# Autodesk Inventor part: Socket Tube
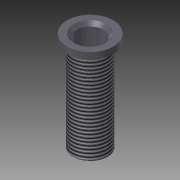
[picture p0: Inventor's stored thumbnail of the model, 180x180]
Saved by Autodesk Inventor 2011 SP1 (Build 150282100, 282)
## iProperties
Created: 2011-10
Part Number: Socket Tube
Document SubType Name: Modeling
Designer: sdarley
Density: 1 g/cm^3
Author: sdarley
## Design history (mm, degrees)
sketch "Sketch1"
  geometry: C1 r 3 at (0, 0) reference; C2 r 3.5 at (0, 0); C3 r 2 at (0, 0); 1 further point
  constraints: 2 centre point, 2 coincident
  dimensions: "d0" = 7 diameter of C2; "d1" = 4 diameter of C3
extrude "Extrusion1" new body sketch "Sketch1" distance "d2" = 1; taper "d3" = 0 deg
sketch "Sketch2"
  geometry: C1 r 2 at (0, 0) reference; C2 r 3.5 at (0, 0) reference; C3 r 2.625 at (0, 0)
  constraints: 1 centre point, 1 coincident
  dimensions: "d4" = 5.25 diameter of C3
extrude "Extrusion2" join sketch "Sketch2" distance "d5" = 14; taper "d6" = 0 deg
chamfer "Chamfer1" distance "d7" = 0.5; stored, may be unused: second distance "d8" = 2, angle "d9" = 45 deg
thread "Thread1" dims "d10" = 10, "d11" = 0
body "Solid1"
node "Reference1"
